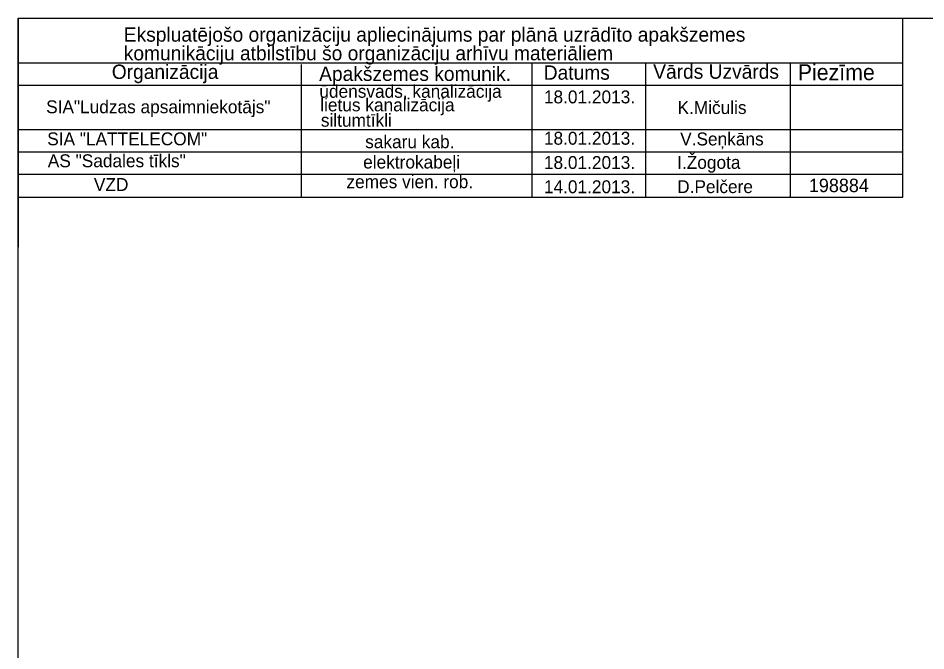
# Model space of a CAD drawing. Extents: x 728710 to 728960, y 272811 to 273475.
# Drawn here: x 728728.9 to 728788.5, y 273433.6 to 273475.1 of the extents above; entities that cross this region are included whole.
import ezdxf

# ---------------------------------------------------------------- set-up
doc = ezdxf.new("R2010")
doc.units = 0
doc.layers.add('RAMI_PLAN_####_TKST_#', color=7, linetype='Continuous')

msp = doc.modelspace()

# ---------------------------------------------------------------- linework, layer by layer
at = {"layer": 'RAMI_PLAN_####_TKST_#'}
for p, q in [((728728.89, 273475.126), (728786.982, 273475.126)), ((728728.89, 273472.194), (728786.982, 273472.194)), ((728747.486, 273463.368), (728747.486, 273472.084)), ((728762.633, 273463.368), (728762.633, 273472.194)), ((728770.107, 273463.368), (728770.107, 273472.121)), ((728779.597, 273463.368), (728779.597, 273472.158)), ((728728.89, 273470.733), (728786.982, 273470.733)), ((728728.89, 273467.809), (728786.982, 273467.809)), ((728728.89, 273466.348), (728786.982, 273466.348)), ((728728.89, 273464.886), (728786.982, 273464.886)), ((728728.89, 273463.369), (728786.982, 273463.368))]:
    msp.add_line(p, q, dxfattribs=at)
msp.add_lwpolyline([(728728.89, 273202.048), (728728.89, 273475.126), (728912.915, 273475.126), (728912.915, 273202.048)], close=True, dxfattribs=at)
for points in [[(728728.89, 273475.126), (728728.89, 273460.076)], [(728786.982, 273463.368), (728786.982, 273475.126)]]:
    msp.add_lwpolyline(points, dxfattribs=at)

# ---------------------------------------------------------------- texts
for s, height, rotation, p in [(' Ekspluatējošo organizāciju apliecinājums par plānā uzrādīto apakšzemes', 0.94182, 359.99995, (728735.477, 273473.58)), (' komunikāciju atbilstību šo organizāciju arhīvu materiāliem', 0.94182, 359.99995, (728735.477, 273472.355)), ('Organizācija', 0.94182, 359.99995, (728735.038, 273471.132)), ('Apakšzemes komunik.', 0.94182, 359.99995, (728748.654, 273471)), ('Datums', 0.9418, 359.99995, (728763.402, 273471.08)), ('Vārds Uzvārds', 0.94182, 359.99995, (728770.59, 273471.144)), ('Piezīme', 1.0465, 359.99995, (728780.084, 273471.05)), ('ūdensvads, kanalizācija', 0.84764, 359.99987, (728748.668, 273469.895)), ('lietus kanalizācija', 0.84764, 359.99974, (728748.726, 273469.003)), ('18.01.2013.', 0.84764, 359.99995, (728763.413, 273469.528)), ('SIA"Ludzas apsaimniekotājs"', 0.84764, 359.99974, (728730.727, 273468.877)), ('K.Mičulis', 0.8476, 359.99974, (728772.185, 273468.828)), ('siltumtīkli', 0.84764, 359.99974, (728748.767, 273467.993)), ('SIA "LATTELECOM"', 0.84764, 359.99974, (728730.798, 273466.771)), ('sakaru kab.', 0.84764, 359.99995, (728751.677, 273466.583)), ('18.01.2013.', 0.84764, 359.99995, (728763.413, 273466.811)), ('V.Seņkāns', 0.8476, 359.99974, (728772.361, 273466.764)), ('I.Žogota', 0.8476, 359.99974, (728772.163, 273465.225)), ('AS "Sadales tīkls"', 0.84764, 359.99974, (728730.837, 273465.331)), ('elektrokabeļi', 0.84764, 359.99974, (728751.545, 273465.247)), ('18.01.2013.', 0.84764, 359.99995, (728763.413, 273465.217)), ('VZD', 0.8476, 359.99974, (728733.864, 273463.771)), ('zemes vien. rob.', 0.84764, 359.99974, (728750.447, 273463.955)), ('14.01.2013.', 0.84764, 359.99995, (728763.413, 273463.624)), ('D.Pelčere', 0.8476, 359.99974, (728772.163, 273463.632))]:
    msp.add_text(s, height=height, rotation=rotation, dxfattribs=at).set_placement(p)
msp.add_text('198884', height=0.883, dxfattribs=at).set_placement((728780.813, 273463.695))

doc.saveas('drawing.dxf')
